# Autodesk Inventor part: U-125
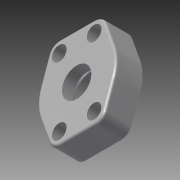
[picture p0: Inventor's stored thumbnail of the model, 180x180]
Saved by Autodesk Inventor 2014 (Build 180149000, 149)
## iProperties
Created: 2011-01
Part Number: U-125
Material: Steel
Document SubType Name: Modeling
Designer: deckm
Density: 7.85 g/cm^3
Description: FLARED FLANGE SAE WITH CLEARANCE HOLES
Mass: 259.498 g
Surface Area: 100.719 cm^2
Volume: 33.0571 cm^3
Appearance: Steel
Author: deckm
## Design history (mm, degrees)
derived "union_cap.ipt"
body "Solid1"
feature "Solid1::union_cap.ipt"
tag "TaggingFeature1"
other parameters: "d1" = 78.994, "d3" = 19.10263, "d25" = 30.226, "FilletTop" = 2, "d27" = 15.875, "d28" = 37 deg, "d29" = 23.114, "d30" = 12.7, "FilletCorners" = 10.16, "FilletEnds" = 36.576, "d8" = 23.114, "d9" = 0, "d12" = 12.7, "d21" = 30.226, "d24" = 58.674
